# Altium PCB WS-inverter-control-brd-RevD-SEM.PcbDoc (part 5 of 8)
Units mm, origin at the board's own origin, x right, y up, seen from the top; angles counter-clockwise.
Board outline 270 x 105.92 mm, 6 copper layers (Top Layer, Int1 (Sign), Int2 (PWR), Int3 (GND), Int4 (Sign), Bottom Layer), stack 1.509 mm thick; 709 components, 375 nets, 2377 pads, 1332 vias.
Unrouted connection lines stored in the file: 55.
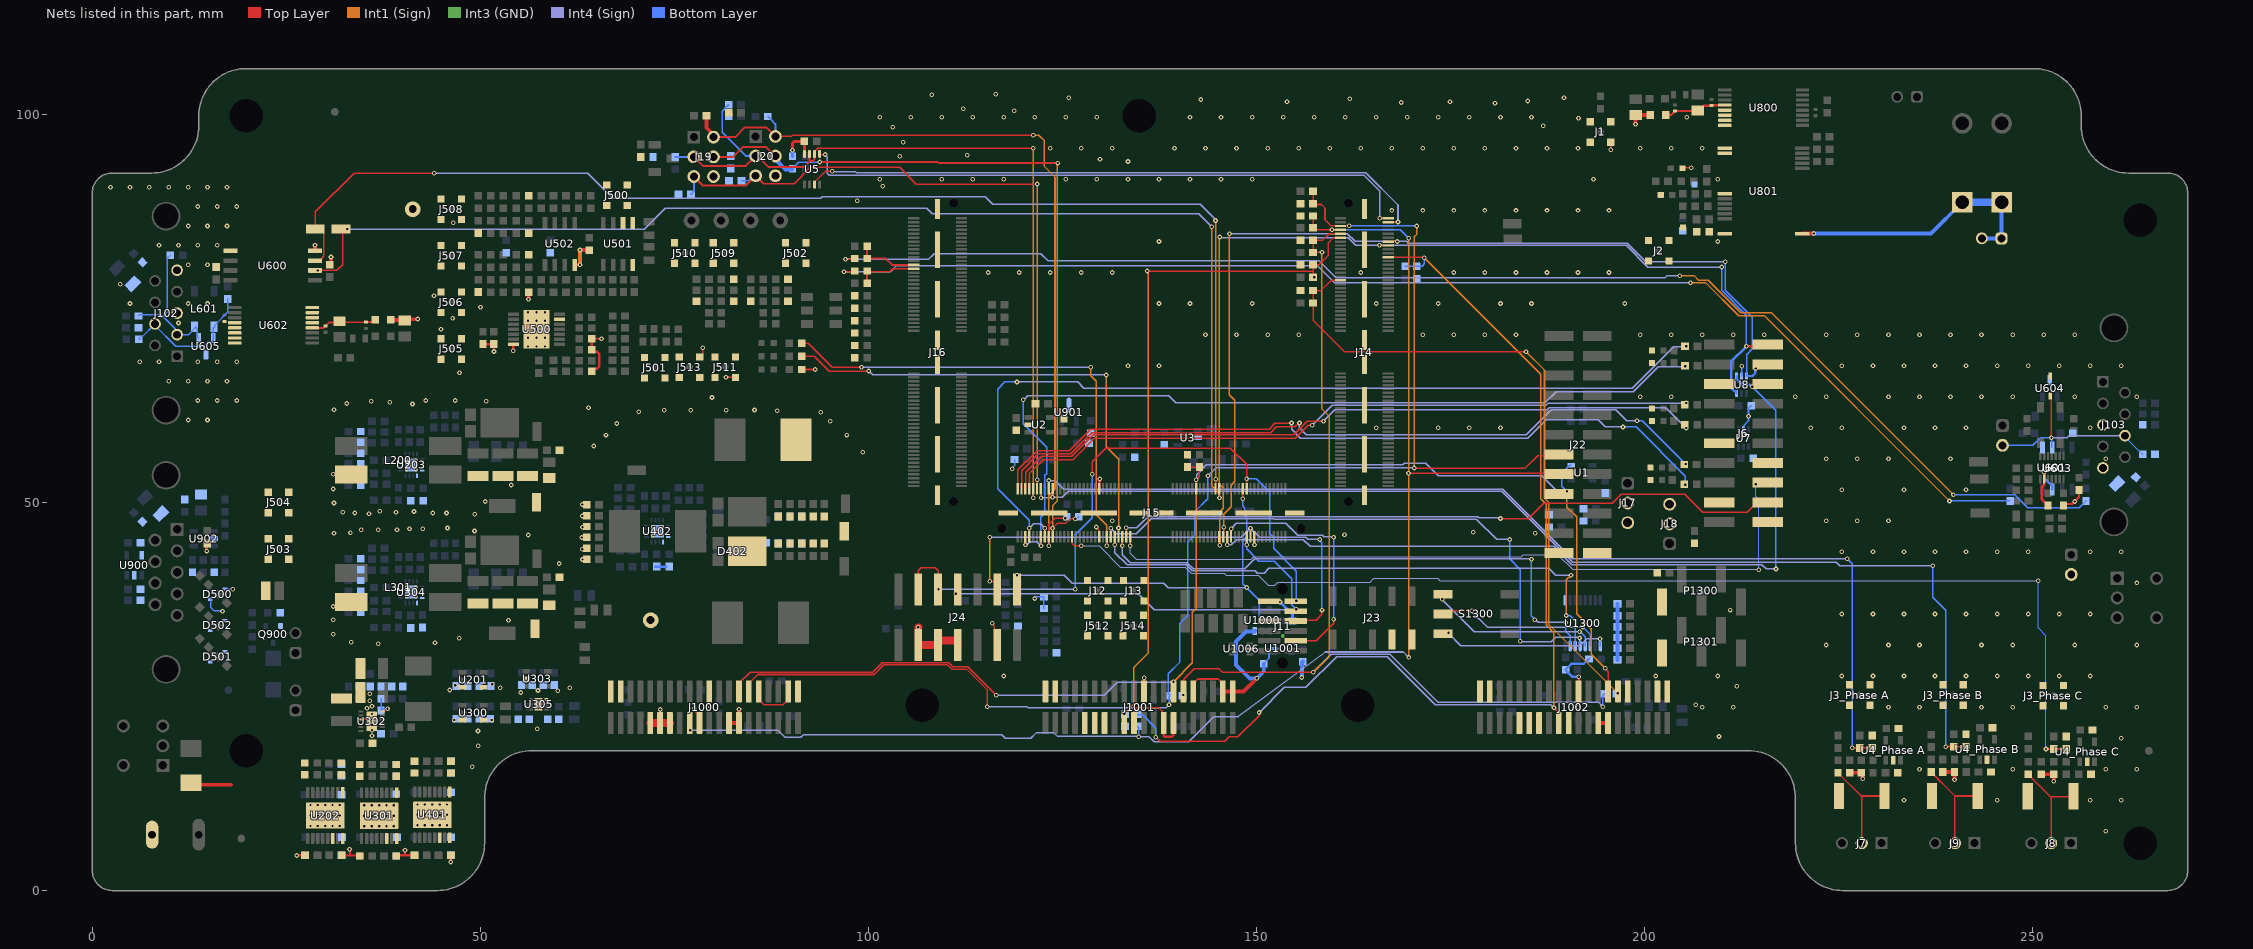
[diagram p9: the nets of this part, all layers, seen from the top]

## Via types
v1: diameter 0.6, hole 0.3, Top Layer to Bottom Layer, tented both sides, 1302 vias
v2: diameter 0.5, hole 0.2, Top Layer to Bottom Layer, 17 vias
v3: diameter 0.6, hole 0.3, Top Layer to Bottom Layer, 12 vias
v4: diameter 0.8, hole 0.5, Top Layer to Bottom Layer, tented both sides, 1 vias

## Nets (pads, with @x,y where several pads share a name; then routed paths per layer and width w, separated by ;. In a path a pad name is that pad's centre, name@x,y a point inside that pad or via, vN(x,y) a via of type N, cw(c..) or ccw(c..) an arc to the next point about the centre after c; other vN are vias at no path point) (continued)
GND: "C8_Phase A.1" "C8_Phase B.1" "C8_Phase C.1" "C10_Phase A.2" "C10_Phase B.2" "C10_Phase C.2" "C11_Phase A.2" "C11_Phase B.2" "C11_Phase C.2" "C12_Phase A.2" "C12_Phase B.2" "C12_Phase C.2" "C13_Phase A.2" "C13_Phase B.2" "C13_Phase C.2" "C14_Phase A.1" "C14_Phase B.1" "C14_Phase C.1" "J3_Phase A.2" "J3_Phase A.3" "J3_Phase A.4" "J3_Phase A.5" "J3_Phase B.2" "J3_Phase B.3" "J3_Phase B.4" "J3_Phase B.5" "J3_Phase C.2" "J3_Phase C.3" "J3_Phase C.4" "J3_Phase C.5" "R23_Phase A.1" "R23_Phase B.1" "R23_Phase C.1" "R24_Phase A.1" "R24_Phase B.1" "R24_Phase C.1" "U4_Phase A.2" "U4_Phase B.2" "U4_Phase C.2" C2.2 C3d1.1 C3d2.1 C3v3ldc2.2 C3v3ldc.2 C4.2 C5.2 C6.1 C6n.1 C7.2 C9.2 C15.2 C16.2 C17.2 C18.2 C19.2 C20.2 C21.2 C22.2 C23.2 C24.2 C100.2 C102.2 C208.2 C209.2 C210.2 C211.2 C212.2 C213.2 C214.2 C215.2 C216.2 C217.2 C218.2 C220.2 C221.2 C222.2 C223.2 C224.2 C225.2 C227.2 C229.1 C230.2 C231.2 C232.2 C233.2 C234.2 C300.2 C301.2 C302.2 C303.2 C304.2 C305.2 C306.2 C307.2 C308.2 C309.2 C310.2 C311.1 C313.2 C314.2 C315.2 C317.2 C318.2 C319.2 C320.2 C321.2 C322.1 C324.2 C325.2 C326.2 C327.2 C328.2 C330.1 C331.2 C332.2 C333.2 C334.2 C335.2 C339.2 C340.2 C341.2 C342.2 C345.2 C346.2 C402.2 C404.2 C406.2 C407.2 C408.2 C409.2 C410.2 C413.2 C414.2 C415.2 C416.2 C417.2 C418.2 C420.1 C421.2 C422.2 C423.1 C424.1 C425.1 C426.1 C427.1 C428.1 C429.2 C431.1 C435.1 C436.1 C437.2 C438.2 C439.2 C440.2 C441.2 C442.2 C503.2 C504.2 C505.2 C506.1 C507.2 C508.1 C511.1 C512.1 C513.2 C516.2 C517.2 C518.2 C519.1 C520.1 C521.2 C522.2 C525.1 C526.1 C528.1 C531.1 C600.2 C602.1 C603.1 C607.2 C609.2 C610.2 C611.1 C612.1 C804.2 C805.2 C810.1 C900.2 C901.1 C902.2 C903.2 C904.2 C905.1 C906.2 C907.2 C908.2 C1000.1 C1001.1 C1002.1 C1300.2 C1301.1 C1302.2 C1303.2 C1304.2 C1305.2 C1306.2 C1307.2 Cu5c.2 D100.2 D402.3 D500.1 D500.4 D501.1 D501.4 D502.1 D502.4 D600.2 FB601.1 FB800.2 J1.2 J1.3 J1.4 J1.5 J2.2 J2.3 J2.4 J2.5 J6.1 J6.4 J6.12 J6.15 J6.18 J11.1 J12.2 J12.3 J12.4 J12.5 J13.2 J13.3 J13.4 J13.5 J14.A1 J14.A2 J14.A3 J14.A4 J14.A5 J14.A6 J14.A7 J14.A8 J15.17 J15.77 J15.78 J15.A1 J15.A2 J15.A3 J15.A4 J15.A5 J15.A6 J15.A7 J15.A8 J16.A1 J16.A2 J16.A3 J16.A4 J16.A5 J16.A6 J16.A7 J16.A8 J17.2 J17.3 J18.2 J18.3 J19.6 J20.6 J22.23 J22.24 J23.2 J23.4 J24.4 J24.8 J24.10 J24.12 J100.2 J103.3 J103.5 J500.2 J500.3 J500.4 J500.5 J501.2 J501.3 J501.4 J501.5 J502.2 J502.3 J502.4 J502.5 J503.2 J503.3 J503.4 J503.5 J504.2 J504.3 J504.4 J504.5 J505.2 J505.3 J505.4 J505.5 J506.2 J506.3 J506.4 J506.5 J507.2 J507.3 J507.4 J507.5 J508.2 J508.3 J508.4 J508.5 J509.2 J509.3 J509.4 J509.5 J510.2 J510.3 J510.4 J510.5 J511.2 J511.3 J511.4 J511.5 J512.2 J512.3 J512.4 J512.5 J513.2 J513.3 J513.4 J513.5 J514.2 J514.3 J514.4 J514.5 J601.2 J1000.2 J1000.4 J1000.9 J1000.11 J1000.13 J1000.19 J1000.22 J1000.25 J1000.27 J1000.32 J1000.38 J1000.40 J1001.2 J1001.4 J1001.9 J1001.11 J1001.13 J1001.19 J1001.22 J1001.25 J1001.27 J1001.32 J1001.38 J1001.40 J1002.2 J1002.4 J1002.9 J1002.11 J1002.13 J1002.19 J1002.22 J1002.25 J1002.27 J1002.32 J1002.38 J1002.40 L200.2 L301.2 L401.1 NT200.1 NT300.1 NT400.1 P1300.5 P1301.5 Q900.2 R5.1 R8.1 R33.1 R34.1 R43.1 R44.1 R45.1 R46.1 R47.1 R48.1 R49.1 R50.1 R51.1 R52.1 R53.1 R54.1 R56.1 R57.1 R58.1 R100.1 R102.1 R238.1 R239.1 R240.1 R241.1 R303.1 R304.1 R305.1 R306.1 R308.1 R320.1 R321.1 R322.1 R406.1 R410.1 R416.1 R417.1 R506.1 R515.2 R533.2 R560.1 R561.1 R903.1 R907.1 R1304.1 TP100.1 TP101.1 TP202.1 TP302.1 TP402.1 TP403.1 U1.2 U2.2 U3.2 U5.4 U7.2 U8.2 U201.3 U201.4 U202.6 U202.8 U202.9 U202.17@30,9.663 U203.1 U203.16 U203.17 U300.3 U300.4 U301.6 U301.8 U301.9 U301.17@36.957,9.643 U302.9 U302.13 U303.2 U304.1 U304.16 U304.17 U305.3 U305.7@57.5,24 U401.6 U401.8 U401.9 U401.17@43.8,9.743 U402.1 U402.16 U402.17 U500.6 U500.14 U500.15 U501.4 U501.5 U501.6 U502.4 U600.4 U601.2 U603.3 U603.5 U604.3 U801.7 U801.8 U801.9 U801.15 U900.2 U900.5 U901.3 U902.2 U1000.3 U1001.2 U1006.2 U1300.9 | length 180.5
  Top Layer w0.18: Cu5c.2@91.743,96.536 Cu5c.2@91.768,96.511
  Top Layer w0.2: U302.9@34.61,22.05 36.03,22.05 v1(36.043,22.036) ; C505.2@51.738,70.411 51.738,69.474 v1(51.747,69.465) ; R506.1@64.344,71.086 65.593,71.086 v1(65.604,71.098) ; J1000.11@73.159,21.588 v1(73.159,23.32) ; J513.4@78.263,68.756 78.633,69.126 78.633,69.926 v1(78.643,69.936) ; v1(79.509,23.836) J1000.22@79.509,25.653 ; v1(81.643,66.136) 81.663,66.116 J511.4@82.863,66.116 ; J1000.32@85.859,25.653 85.859,24.626 86.543,23.943 88.986,23.943 89.669,24.626 J1000.38@89.669,25.653 ; R8.1@91.414,67.136 v1(93.143,67.136) ; v1(115.943,34.436) 116.243,34.136 116.243,31.986 J24.4@116.593,31.636 ; v1(129.343,46.836) 129.681,46.499 129.681,45.637 J15.77@129.733,45.585 ; J15.78@129.733,51.757 129.783,51.807 129.783,52.986 v1(129.833,53.036) ; J1001.19@134.239,21.588 134.239,23.241 134.541,23.543 137.436,23.543 137.839,23.14 137.839,21.798 J1001.25@138.049,21.588 ; J1001.32@141.859,25.653 141.859,26.681 142.431,27.253 145.097,27.253 145.669,26.681 J1001.38@145.669,25.653 ; U1006.2@149.168,31.136 v1(149.729,31.136) ; J15.17@149.733,45.585 149.743,45.575 149.738,45.57 149.738,44.541 v1(149.743,44.536) ; J11.1@151.65,37.258 151.721,37.187 v1(153.039,37.187) ; v1(195.643,95.436) J1.5@195.643,96.436 ; C6.1@204.9,93.078 204.959,93.136 v1(206.043,93.136)
  Top Layer w0.3: v1(14.744,43.739) 14.744,44.652 C905.1@14.808,44.717 ; v1(26.328,4.521) 26.37,4.563 C209.2@27.4,4.563 ; C208.2@32.125,4.563 32.185,4.503 33.194,4.503 ; v1(33.143,5.336) 33.194,5.285 33.194,4.503 ; C301.2@34.468,4.443 34.408,4.503 33.194,4.503 ; C300.2@39.168,4.443 39.268,4.543 40.291,4.543 ; v1(40.291,5.184) 40.291,4.543 ; C404.2@41.5,4.543 40.291,4.543 ; v1(46.2,3.68) C402.2@46.2,4.543 ; C504.2@50.338,70.411 C505.2@51.738,70.411 ; v1(54.22,69.562) 54.22,70.293 U500.14@54.288,70.361 ; C503.2@64.344,66.911 64.669,67.236 65.017,67.236 65.334,67.553 65.334,69.146 65.073,69.407 64.624,69.407 C506.1@64.344,69.686 R506.1@64.344,71.086 ; v1(77.543,23.436) 77.543,23.312 78.239,22.616 J1000.19@78.239,21.588 ; J1001.22@135.509,25.653 135.543,25.688 v1(135.543,27.436) ; J1001.25@138.049,21.588 138.049,19.951 138.2,19.8 139.1,19.8 139.319,20.019 J1001.27@139.319,21.588 ; J1002.22@191.509,25.653 191.526,25.671 191.526,27.509 v1(191.543,27.526) ; v1(251.483,53.896) 251.5,53.88 U601.2@251.5,53 251.5,52.295 251.211,52.007 251.211,50.389 251.65,49.95 251.675,49.95 252,49.625 C602.1@252,49.6 ; C612.1@254,49.6 254.195,49.795 255.102,49.795 256,50.693 C611.1@256,51.6
  Top Layer w0.35: U5.4@91.768,94.911 Cu5c.2@91.768,96.511
  Top Layer w0.4: v1(90.225,95.398) 90.225,96.27 90.491,96.536 Cu5c.2@91.743,96.536
  Top Layer w0.5: D100.2@12.7,13.89 12.954,13.636 17.843,13.636 ; v1(28.689,83.163) 28.689,82.445 U600.4@28.693,82.441 ; C600.2@30.601,80.649 30.743,80.791 v1(30.743,81.636) ; FB601.1@38.343,73.536 38.377,73.502 40.009,73.502 40.043,73.468 40.192,73.617 41.924,73.617 v1(41.943,73.636) ; v1(56.193,76.185) 56.213,76.204 56.213,77.085 C507.2@56.238,77.111 ; U502.4@62.143,80.611 62.168,80.636 v1(62.843,80.636) ; v1(62.843,82.536) 64.013,82.536 C518.2@64.038,82.511 ; J1000.25@82.049,21.588 J1000.27@83.319,21.588 83.324,21.594 83.324,23.355 v1(83.33,23.36) ; J1001.38@145.669,25.653 J1001.40@146.939,25.653 148.36,25.653 v1(150.043,27.336) ; J1002.25@194.049,21.588 J1002.27@195.319,21.588 ; v1(198.843,98.736) 198.843,99.786 198.978,99.92 FB800.2@200.827,99.92 ; 226.45,15.178 227.95,15.178 228.131,14.997 228.112,14.978 v1(228.112,14.396) ; 238.45,15.278 239.95,15.278 v1(239.951,14.289) ; 251.15,14.978 252.75,14.978 252.758,14.97 v1(252.758,14.086)
  Top Layer w1: J1000.9@71.889,21.588 J1000.11@73.143,21.588 ; J1000.11@73.159,21.588 J1000.13@74.429,21.588 ; v1(106.443,33.936) 106.433,33.926 J24.12@106.433,31.636 J24.10@108.973,31.636 108.973,32.231 111.513,32.231 J24.8@111.513,31.636
  Int3 (GND) w0.2: v1(16.774,35.974) v1@16.812,35.936
  Int3 (GND) w0.5: 153.392,32.785 153.392,32.813
  Int1 (Sign) w0.5: v1(62.843,80.636) v1(62.843,82.536)
  Bottom Layer w0.2: D500.1@15.2,37.549 15.234,37.515 15.234,36.508 15.691,36.051 16.698,36.051 v1(16.774,35.974) ; D500.4@17.1,38.849 17.106,38.843 18.096,38.843 v1(18.102,38.836) ; v1(118.524,54.357) 118.524,54.442 118.843,54.761 C508.1@118.843,55.536 ; v1(121.443,37.636) 121.649,37.842 C512.1@122.618,37.842 C519.1@122.618,36.342 ; C1002.1@150.949,29.218 150.949,29.243 151.624,29.918 151.624,30.771 151.79,30.938 151.794,30.938 152.044,31.188 U1001.2@152.269,31.188 ; U8.2@212.523,66.299 212.523,67.516 v1(212.543,67.536) ; U7.2@212.773,59.424 212.847,59.498 212.847,59.97 213.412,60.535 213.412,62.136 C23.2@213.752,62.477
  Bottom Layer w0.3: v1(14.744,43.739) 14.744,44.677 15.02,44.953 15.067,44.953 15.243,45.129 15.243,45.203 15.393,45.353 U902.2@15.643,45.353 ; C429.2@72.543,41.736 C420.1@73.943,41.736 ; R1304.1@189.843,28.436 189.843,28.411 190.728,27.526 v1(191.543,27.526) ; R1304.1@189.843,28.461 190.59,29.209 192.19,29.209 192.818,29.836 C1300.2@192.843,29.836 ; v1(251.483,53.896) 251.541,53.839 251.541,53.135 252.351,52.325 252.415,52.325 252.565,52.175 U603.3@252.565,51.7
  Bottom Layer w0.4: R57.1@90.221,94.602 v1@90.221,95.402 ; v1(153.039,37.187) 154.643,35.583 C1000.1@154.643,34.736
  Bottom Layer w0.5: 148.038,32.711 147.393,32.067 147.393,29.083 149.14,27.336 v1(150.043,27.336) 150.949,28.242 C1002.1@150.949,29.218 ; 148.038,32.712 148.682,33.356 149.744,33.356 149.794,33.406 U1000.3@149.794,33.438 ; v1(155.852,27.456) 155.871,27.475 155.871,29.365 C1001.1@155.994,29.488 ; C1305.2@196.543,29.714 C1306.2@196.543,31.2 C1307.2@196.543,32.6 C1304.2@196.543,34 C1303.2@196.543,35.4 C1302.2@196.543,36.936
  other v1: 259.443,7.636 35.057,8.293 36.007,8.293 36.957,8.293 37.907,8.293 38.857,8.293 28.1,8.313 29.05,8.313 30,8.313 30.95,8.313 31.9,8.313 41.9,8.393 42.85,8.393 43.8,8.393 44.75,8.393 45.7,8.393 28.1,9.663 31.9,9.663 35.057,9.643 38.857,9.643 41.9,9.743 45.7,9.743 35.057,10.993 36.007,10.993 36.957,10.993 37.907,10.993 38.857,10.993 28.1,11.013 29.05,11.013 30,11.013 30.95,11.013 31.9,11.013 41.9,11.093 42.85,11.093 43.8,11.093 44.75,11.093 45.7,11.093 233.443,11.636 245.443,11.636 257.443,11.636 261.443,11.636 235.443,15.636 247.443,15.636 259.443,15.636 263.443,15.636 48.943,15.936 49.743,18.636 261.443,19.636 209.616,19.853 36.043,19.936 49.698,20.552 36.043,20.636 57.343,20.836 36.043,21.336 46.649,21.962 51.449,21.962 36.043,22.736 35.391,23.498 191.443,23.636 207.443,23.636 211.443,23.636 231.443,23.636 235.443,23.636 243.443,23.636 247.443,23.636 259.443,23.636 263.443,23.636 36.043,23.736 206.606,23.936 35.743,24.436 35.743,25.336 55.202,25.521 59.956,25.743 57.43,25.777 46.043,25.836 61.523,26.119 52.543,26.136 211.906,26.336 46.743,26.436 51.528,26.6 117.443,27.636 201.443,27.636 209.443,27.636 225.443,27.636 229.443,27.636 233.443,27.636 237.443,27.636 241.443,27.636 245.443,27.636 249.443,27.636 253.443,27.636 257.443,27.636 223.443,31.636 231.443,31.636 235.443,31.636 243.443,31.636 247.443,31.636 255.443,31.636 263.443,31.636 36.86,31.808 44.16,31.908 33.36,32.008 47.26,32.508 31.06,33.008 53.63,34.829 31.06,34.908 225.443,35.636 229.443,35.636 233.443,35.636 237.443,35.636 241.443,35.636 245.443,35.636 249.443,35.636 253.443,35.636 257.443,35.636 211.043,36.136 31.06,36.608 263.443,39.636 60.143,42.136 63.157,42.647 225.443,43.636 229.443,43.636 233.443,43.636 237.443,43.636 241.443,43.636 245.443,43.636 249.443,43.636 257.443,43.636 261.443,43.636 63.12,43.991 63.074,45.494 56.16,45.808 161.343,45.836 185.943,46.036 31.144,46.053 33.254,46.104 177.936,46.177 49.243,46.336 34.66,46.508 36.86,46.508 39.26,46.508 40.86,46.608 42.56,46.608 45.76,46.708 63.159,46.805 131.443,47.636 223.443,47.636 227.443,47.636 231.443,47.636 63.108,48.252 49.272,48.488 35.643,48.536 33.792,48.651 43.872,48.646 45.643,48.636 39.134,48.725 32.275,48.758 41.443,48.836 37.027,48.876 63.143,49.736 31.143,49.936 50.643,50.136 255.443,50.136 225.443,51.636 233.443,51.636 241.443,51.636 31.043,51.736 53.985,52.248 31.043,53.636 223.443,55.636 227.443,55.636 231.443,55.636 239.443,55.636 259.443,55.636 99.293,56.486 64.593,57.286 66.193,58.686 97.193,58.686 165.443,59.636 173.443,59.636 177.443,59.636 181.443,59.636 221.443,59.636 225.443,59.636 233.443,59.636 237.443,59.636 241.443,59.636 257.443,59.636 67.593,60.186 95.093,60.486 213.412,61.105 93.843,61.636 70.393,61.686 88.243,61.836 73.693,61.886 77.093,61.886 81.693,61.886 31.143,61.936 85.317,61.916 63.937,62.227 41.261,62.692 32.788,62.75 38.343,62.936 35.94,63.046 50.744,63.053 42.943,63.136 46.743,63.136 79.843,63.536 199.443,63.636 203.443,63.636 219.443,63.636 223.443,63.636 231.443,63.636 235.443,63.636 239.443,63.636 243.443,63.636 247.443,63.636 255.443,63.636 263.443,63.636 47.319,66.738 133.443,67.636 137.443,67.636 225.443,67.636 229.443,67.636 233.443,67.636 237.443,67.636 241.443,67.636 245.443,67.636 249.443,67.636 253.443,67.636 257.443,67.636 261.443,67.636 56.138,70.111 57.238,70.111 58.338,70.111 56.138,71.211 58.338,71.211 143.443,71.636 147.443,71.636 151.443,71.636 155.443,71.636 171.443,71.636 175.443,71.636 179.443,71.636 183.443,71.636 199.443,71.636 203.443,71.636 207.443,71.636 211.443,71.636 215.443,71.636 223.443,71.636 227.443,71.636 231.443,71.636 235.443,71.636 239.443,71.636 243.443,71.636 247.443,71.636 251.443,71.636 255.443,71.636 56.138,72.311 58.338,72.311 44.919,72.338 56.138,73.411 58.338,73.411 46.419,73.738 56.138,74.511 57.238,74.511 58.338,74.511 50.019,75.138 137.443,75.636 141.443,75.636 149.443,75.636 165.443,75.636 173.443,75.636 181.443,75.636 185.443,75.636 197.443,75.636 44.019,76.638 115.443,79.636 119.443,79.636 123.443,79.636 127.443,79.636 131.443,79.636 163.443,79.636 175.443,79.636 179.443,79.636 183.443,79.636 187.443,79.636 191.443,79.636 195.443,79.636 137.443,83.636 209.443,83.636 46.511,86.044 167.443,87.636 171.443,87.636 175.443,87.636 179.443,87.636 183.443,87.636 187.443,87.636 191.443,87.636 195.443,87.636 98.55,88.873 101.843,90.736 101.443,91.636 109.443,91.636 113.443,91.636 117.443,91.636 125.443,91.636 129.443,91.636 133.443,91.636 137.443,91.636 141.443,91.636 145.443,91.636 149.443,91.636 193.443,91.636 209.443,91.636 133.443,93.936 129.843,94.236 104.043,94.636 112.743,94.736 123.443,95.636 127.443,95.636 131.443,95.636 139.443,95.636 143.443,95.636 147.443,95.636 151.443,95.636 155.443,95.636 159.443,95.636 163.443,95.636 167.443,95.636 171.443,95.636 175.443,95.636 179.443,95.636 183.443,95.636 187.443,95.636 191.443,95.636 199.443,95.636 203.443,95.636 207.443,95.636 104.502,96.413 103.143,98.336 186.943,98.536 191.51,99.502 101.443,99.636 105.443,99.636 109.443,99.636 113.443,99.636 117.443,99.636 121.443,99.636 125.443,99.636 129.443,99.636 141.443,99.636 145.443,99.636 149.443,99.636 153.443,99.636 157.443,99.636 161.443,99.636 165.443,99.636 169.443,99.636 173.443,99.636 177.443,99.636 181.443,99.636 185.443,99.636 205.443,99.636 118.798,100.478 112.243,100.736 180.743,101.436 168.643,101.536 153.943,101.636 174.943,101.636 184.943,101.736 142.843,101.936 162.043,102.036 189.643,102.136 125.825,102.166 108.143,102.536 116.421,102.613
  other v2: 57.5,23.45 57.5,24.55 40.52,37.87 41.68,37.87 41.1,38.45 40.52,39.03 41.68,39.03 72.22,45.72 73.343,45.836 72.8,46.3 72.22,46.88 73.38,46.88 40.52,54.27 41.68,54.27 41.1,54.85 40.52,55.43 41.68,55.43
  other v3: 29.05,9.663 30,9.663 30.95,9.663 36.007,9.643 36.957,9.643 37.907,9.643 42.85,9.743 43.8,9.743 44.75,9.743 57.238,71.211 57.238,72.311 57.238,73.411
GND_ISO: C101.2 C601.2 C604.1 C608.2 C614.1 J102.3 J102.5 R101.1 U600.5 U602.12 U602.13 U602.14 U602.15 U602.16 U605.3
  other v1: 12.343,60.636 14.843,60.636 13.593,63.136 16.093,63.136 18.593,63.136 9.843,65.636 12.343,65.636 14.843,65.636 17.343,65.636 6.093,68.136 8.593,68.136 13.593,68.136 16.093,68.136 18.593,68.136 11.093,73.136 4.843,75.636 12.343,75.636 14.843,75.636 3.593,78.136 12.343,80.636 14.843,80.636 8.593,83.136 11.093,83.136 13.593,83.136 16.093,83.136 12.343,85.636 14.843,85.636 17.343,85.636 13.593,88.136 16.093,88.136 18.593,88.136 2.343,90.636 4.843,90.636 7.343,90.636 9.843,90.636 12.343,90.636 14.843,90.636 17.343,90.636
GNDP: C605.1 C606.2 C613.1 FB601.2 U602.4 U602.5 U602.6 U602.7 U602.8 | length 8.8
  Top Layer w0.25: U602.4@28.343,72.511 29.768,72.511 29.993,72.736 30.093,72.736 30.168,72.811 30.168,72.861 30.474,73.167 31.658,73.167 C606.2@31.843,73.352 31.968,73.227 C605.1@35.234,73.227 ; C605.1@35.243,73.236 36.368,73.236 36.543,73.411 FB601.2@36.543,73.536
GNDP1: C800.2 C801.2 C802.1 FB800.1 U800.4 U800.5 U800.6 U800.7 U800.8 | length 8.3
  Top Layer w0.3: FB800.1@202.643,99.936 203.443,99.936 203.843,100.336 203.843,100.386 203.893,100.436 C801.2@203.943,100.436 206.759,100.436 C802.1@206.843,100.52 207.008,100.52 207.624,101.136 C800.2@208.643,101.136 208.693,101.186 208.902,101.186 208.918,101.203 U800.4@210.35,101.203
HSEC101_13: S1300.6 U1300.1 | length 21.7
  Int4 (Sign) w0.2: v1(174.743,33.236) 174.743,33.136 176.343,31.536 191.676,31.536 192.594,32.455 v1(194.278,32.455)
  Bottom Layer w0.2: v1(194.278,32.455) 194.325,32.455 U1300.1@194.325,31.5
HSEC103_13: S1300.5 U1300.3 | length 21.9
  Top Layer w0.2: S1300.5@174.043,35.636 174.443,36.036 v1(177.743,36.036)
  Int4 (Sign) w0.2: v1(177.743,36.036) 177.743,35.955 177.882,35.816 177.882,35.797 179.73,33.95 v1(192.05,33.95)
  Bottom Layer w0.2: v1(192.05,33.95) 193.025,32.975 U1300.3@193.025,31.5
HSEC105_13: S1300.4 U1300.4 | length 22.4
  Top Layer w0.2: v1(173.943,37.536) 173.943,38.076 S1300.4@174.043,38.176
  Int4 (Sign) w0.2: v1(173.943,37.536) 173.943,37.453 178.06,33.336 v1(191.643,33.336)
  Bottom Layer w0.2: v1(191.643,33.336) 191.741,33.336 192.375,32.702 U1300.4@192.375,31.5
HV: J5.1 J5.2 J107.1 J108.1 U801.1 | length 34.6
  Top Layer w0.5: U801.1@220.325,84.653 v1(221.8,84.653)
  Bottom Layer w0.5: v1(221.8,84.653) 236.916,84.653 J108.1@240.952,88.689 ; J5.2@243.473,84.036 J5.1@246.013,84.036 246.013,88.67 J107.1@246.032,88.689
  Bottom Layer w1: J108.1@240.952,88.689 J107.1@246.032,88.689
IFB_I2C_SCL: J6.3 J15.61 | length 95.7
  Top Layer w0.18: v1(133.733,44.446) J15.61@133.733,45.585
  Top Layer w0.25: J6.3@214.298,52.339 214.3,52.336 v1(214.343,52.336)
  Int4 (Sign) w0.16: v1(133.733,44.446) 133.733,43.446 134.497,42.682 149.32,42.682 149.644,43.006 184.096,43.006 184.359,43.27 188.861,43.27 190.759,41.373 214.707,41.373 v1(214.743,41.336)
  Bottom Layer w0.16: v1(214.343,52.336) 214.343,50.836 214.743,50.436 v1(214.743,41.336)
IFB_I2C_SDA: J6.2 J15.63 | length 87.2
  Top Layer w0.18: J15.63@133.233,45.585 v1(133.233,46.746) ; v1(181.443,47.936) 185.046,47.936 186.995,49.886 195.859,49.886 197.009,51.036 205.224,51.036 207.506,48.754 207.506,48.736 213.248,48.736 214.528,50.016 J6.2@215.863,50.016
  Int4 (Sign) w0.18: v1(133.233,46.746) 134.585,46.746 135.996,48.157 152.329,48.157 152.34,48.146 178.533,48.146 178.663,48.017 181.363,48.017 v1(181.443,47.936)
IFB_U: "C13_Phase A.1" "R20_Phase A.2" J15.104 | length 135.3
  Top Layer w0.18: J15.104@123.233,51.757 v1(123.233,52.826)
  Top Layer w0.2: 227.75,18.378 229.35,18.378
  Top Layer w0.25: v1(226.785,18.378) 227.75,18.378
  Int4 (Sign) w0.18: v1(123.233,52.826) 124.11,52.826 125.205,51.732 131.466,51.732 131.469,51.729 181.736,51.729 190.728,42.736 v1(226.143,42.736)
  Bottom Layer w0.18: v1(226.143,42.736) 226.785,42.095 v1(226.785,18.378)
IFB_U_1_N: "R1_Phase A.1" J15.118 | length 95.8
  Top Layer w0.18: J15.118@119.733,51.757 119.733,54.078 121.911,56.255 126.056,56.255 128.801,59 151.821,59 152.567,59.746 154.951,59.746 155.441,60.236 v1(155.543,60.236)
  Top Layer w0.381: v1(205.314,54.957) v1@205.373,54.899
  Int4 (Sign) w0.18: v1(155.543,60.236) 155.616,60.163 155.543,60.09 155.543,59.618 156.411,58.75 184.767,58.75 184.78,58.738 187.994,61.952 196.328,61.952 197.743,60.536 v1(199.043,60.536)
  Bottom Layer w0.18: v1(199.043,60.536) 199.735,60.536 v1(205.314,54.957)
IFB_U_1_P: "R3_Phase A.1" J15.120 | length 97.4
  Top Layer w0.18: J15.120@119.233,51.757 119.233,54.192 121.731,56.689 125.876,56.689 128.621,59.434 151.641,59.434 152.387,60.18 154.471,60.18 v1(154.527,60.236)
  Top Layer w0.381: v1(205.278,52.266) v1@205.278,52.365
  Int4 (Sign) w0.18: v1(154.527,60.236) 154.558,60.205 154.558,59.421 155.676,58.304 184.977,58.304 185.095,58.422 187.334,60.661 194.018,60.661 194.943,59.736 v1(197.243,59.736)
  Bottom Layer w0.18: v1(197.243,59.736) 198.921,59.736 205.278,53.379 v1(205.278,52.266)
IFB_V: "C13_Phase C.1" "R20_Phase C.2" J15.91 | length 152.8
  Top Layer w0.2: J15.91@126.233,45.585 126.286,45.532 126.286,44.694 126.543,44.436 v1(127.443,44.436) ; 252.743,18.236 254.343,18.236
  Top Layer w0.25: v1(251.743,18.236) 252.743,18.236
  Int4 (Sign) w0.16: v1(127.443,44.436) 127.453,44.446 129.716,44.446 132.482,41.68 140.83,41.68 141.602,40.908 145.872,40.908 146.145,40.635 150.224,40.635 151.522,39.336 152.343,39.336 152.743,39.736 153.312,39.736 cw(c153.365,38.848) 153.418,39.736 164.643,39.736 165.143,40.236 173.343,40.236 173.643,39.936 v1(250.743,39.936)
  Bottom Layer w0.16: v1(250.743,39.936) 250.743,33.83 251.743,32.83 v1(251.743,18.236)
IFB_V_1_N: "R1_Phase C.1" J15.114 | length 90.6
  Top Layer w0.2: J15.114@120.733,51.757 120.743,51.767 120.743,52.836 120.743,53.736 122.525,55.518 126.372,55.518 129.131,58.277 155.001,58.277 156.677,59.952 v1(157.195,59.952)
  Top Layer w0.381: v1@205.373,62.599 v1(205.373,62.813)
  Int4 (Sign) w0.2: v1(157.195,59.952) 159.782,62.54 187.285,62.54 187.558,62.813 v1(205.373,62.813)
IFB_V_1_P: "R3_Phase C.1" J15.116 | length 92.2
  Top Layer w0.18: J15.116@120.233,51.757 120.253,51.777 120.253,53.874 122.341,55.962 126.188,55.962 128.947,58.72 154.817,58.72 156.565,60.469 v1(158.64,60.469)
  Top Layer w0.381: v1(205.373,59.599) 205.373,59.999
  Int4 (Sign) w0.18: v1(158.64,60.469) 160.107,61.936 187.45,61.936 187.745,62.232 202.74,62.232 v1(205.373,59.599)
IFB_VOC_U: J6.8 J15.31 U8.1 | length 101.9
  Top Layer w0.18: v1(146.233,44.546) J15.31@146.233,45.585
  Top Layer w0.3: v1@213.873,65.174 v1(213.873,64.926) 213.986,65.039 J6.8@214.298,65.039
  Int4 (Sign) w0.18: v1(146.233,44.546) 146.789,44.546 147.467,45.224 148.152,45.224 156.055,45.225 156.943,44.336 188.336,44.336 190.665,42.008 215.094,42.008 215.666,41.436 v1(216.943,41.436)
  Bottom Layer w0.18: v1(213.873,64.926) 216.943,61.855 v1(216.943,41.436)
  Bottom Layer w0.3: U8.1@211.864,66.291 211.923,66.233 211.923,65.857 212.566,65.214 213.547,65.214 213.835,64.926 v1(213.873,64.926)
IFB_VOC_V: J6.10 J14.106 J15.35 U8.6 | length 128.7
  Top Layer w0.18: J15.35@145.233,45.585 145.246,45.572 145.246,44.504 v1(145.26,44.49) ; v1(165.865,83.136) 165.872,83.129 166.994,83.129 J14.106@167.001,83.122
  Top Layer w0.3: v1(213.141,70.119) J6.10@214.298,70.119
  Int1 (Sign) w0.18: v1(145.26,44.49) 145.26,48.753 145.743,49.236 145.743,51.872 145.242,52.373 145.242,84.194 v1(145.264,84.216)
  Int4 (Sign) w0.18: v1(145.264,84.216) 145.343,84.136 161.832,84.136 162.832,83.136 v1(165.865,83.136) 197.643,83.136 200.443,80.336 v1(209.943,80.336)
  Bottom Layer w0.18: v1(209.943,80.336) 209.943,77.336 213.141,74.138 v1(213.141,70.119)
  Bottom Layer w0.3: U8.6@211.873,64.049 211.873,64.274 211.823,64.324 211.598,64.324 211.173,64.749 211.173,68.15 v1(213.141,70.119)
IFB_VOC_W: J6.9 J14.108 J15.33 U8.3 | length 124.9
  Top Layer w0.18: J15.33@145.733,45.585 145.76,45.612 145.76,46.791 v1(145.787,46.818) ; J14.108@167.001,83.622 167.016,83.636 v1(168.143,83.636)
  Int1 (Sign) w0.18: v1(145.787,46.818) 145.787,48.481 146.743,49.436 146.743,50.261 146.739,50.265 146.739,52.232 147.223,52.716 147.223,63.156 146.525,63.855 v1(146.525,84.645)
  Int4 (Sign) w0.18: v1(146.525,84.645) 161.719,84.645 162.728,83.636 v1(168.143,83.636) 169.35,83.636 169.57,83.416 197.759,83.416 197.839,83.336 197.843,83.336 200.143,81.036 210.443,81.036 v1(210.429,81.022)
  Bottom Layer w0.18: v1@210.437,81.013 210.437,77.339 213.893,73.883 213.893,69.786 213.173,69.066 U8.3@213.173,66.299
  Bottom Layer w0.3: U8.3@213.173,66.299 213.921,66.299 214.282,66.659 214.282,67.204 v1(214.339,67.261)
IFB_W: "C13_Phase B.1" "R20_Phase B.2" J15.102 J15.108 | length 148.1
  Top Layer w0.18: J15.108@122.233,51.757 122.243,51.747 122.243,50.631 v1(122.253,50.621) ; v1(123.733,50.663) J15.102@123.733,51.757
  Top Layer w0.2: 239.843,18.536 241.443,18.536
  Top Layer w0.25: v1(238.843,18.536) 239.843,18.536
  Int4 (Sign) w0.18: v1(122.253,50.621) 122.274,50.642 123.712,50.642 v1(123.733,50.663) 124.978,50.663 125.767,51.452 131.35,51.452 131.353,51.449 181.62,51.449 190.781,42.288 224.693,42.288 225.145,41.836 v1(237.143,41.836)
  Bottom Layer w0.18: v1(237.143,41.836) 237.143,37.788 238.843,36.088 v1@238.843,18.617 ; v1@238.763,18.617 v1(238.843,18.536)
IFB_W_1_N: "R1_Phase B.1" J15.105 J15.113 | length 116.1
  Top Layer w0.18: J15.113@120.733,45.585 v1(120.733,46.687) ; J15.105@122.733,45.585 v1(122.733,46.689)
  Top Layer w0.381: v1@205.343,70.136 v1(205.37,70.136)
  Int4 (Sign) w0.18: v1(119.143,65.536) 126.969,65.536 127.769,64.736 198.404,64.736 203.759,70.092 v1@205.499,70.092 ; v1(120.733,46.687) 121.29,47.244 122.178,47.244 v1(122.733,46.689)
  Bottom Layer w0.18: v1(119.143,65.536) 117.564,65.536 116.643,64.616 116.643,51.8 120.733,47.71 v1(120.733,46.687)
IFB_W_1_P: "R3_Phase B.1" J15.107 J15.115 | length 113
  Top Layer w0.18: J15.115@120.233,45.585 120.238,45.58 120.238,44.541 v1(120.243,44.536) ; v1(122.233,44.446) J15.107@122.233,45.585
  Top Layer w0.381: v1(205.268,67.561) v1@205.343,67.636
  Int4 (Sign) w0.18: v1(119.943,63.236) 120.031,63.236 120.553,63.758 138.675,63.758 139.603,62.83 187.164,62.83 188.637,64.302 198.583,64.302 201.805,67.524 v1@205.398,67.524 ; v1(120.243,44.536) 120.304,44.598 120.471,44.598 120.838,44.965 121.714,44.965 v1(122.233,44.446)
  Bottom Layer w0.18: v1(119.943,63.236) 119.972,63.208 119.972,60.132 122.968,57.136 122.968,53.705 122.743,53.48 122.743,48.594 122.233,48.084 v1(122.233,44.446)
ILEM_A_1: "R21_Phase A.1" "R23_Phase A.2" J7.2 | length 14.4
  Top Layer w0.2: 224.95,15.178 224.95,15.153 227.925,12.178 ; J7.2@228.003,6.103 228.003,12.1 227.925,12.178 ; 230.953,11.128 230.953,12.178 227.925,12.178
ILEM_B_1: "R21_Phase C.1" "R23_Phase C.2" J8.2 | length 13.1
  Top Layer w0.2: 249.45,14.978 249.45,14.953 252.343,12.06 ; J8.2@252.403,6.103 252.403,12 252.343,12.06 ; 255.293,12.136 255.217,12.06 252.343,12.06
"ILEM_B_Phase B": "R21_Phase B.1" "R23_Phase B.2" J9.2 | length 13.4
  Top Layer w0.2: 236.95,15.278 236.95,15.253 240.025,12.178 ; J9.2@240.003,6.103 240.003,12.156 240.025,12.178 ; 242.953,12.178 240.025,12.178
ISOCAN_H_1: J102.7 L601.3 R601.2 R603.2 U605.2 | length 18.2
  Bottom Layer w0.2: R603.2@5.968,71.021 6.343,71.396 6.461,71.396 7.977,72.912 J102.7@8.08,73.015 8.08,72.8 10.743,70.136 14.336,70.136 14.887,70.687 15.393,70.687 15.593,70.887 U605.2@15.593,71.186 15.593,72.461 15.793,72.661 15.793,72.886 17.443,74.536 R601.2@17.443,76.236
ISOCAN_L_1: J102.2 L601.4 R607.1 R610.2 U605.1 | length 19.2
  Bottom Layer w0.2: R607.1@5.943,74.036 6.112,74.205 8.859,74.205 9.065,73.999 ; R610.2@10.043,81.836 10.018,81.836 9.643,81.461 9.648,81.461 9.648,74.582 9.065,73.999 ; U605.1@13.693,71.186 13.532,71.348 13.532,72.423 13.356,72.599 13.293,72.661 13.293,72.536 12.387,71.63 J102.2@10.92,71.63 10.671,71.879 10.671,72.393 9.065,73.999
LDC_COS: J15.103 J19.2 J20.2 R31.1 R35.1 Rjldc2.2 | length 108.3
  Top Layer w0.2: J20.2@88.013,97.176 90.083,97.176 90.243,97.336 v1(121.243,97.336) ; v1(123.233,44.446) J15.103@123.233,45.585 123.233,47.163 124.021,47.951 v1(125.354,47.951)
  Top Layer w0.25: J19.2@80.043,97.076 82.828,97.076 84.078,98.326 86.863,98.326 J20.2@88.013,97.176
  Top Layer w0.5: R31.1@79.143,99.836 79.143,98.288 80.043,97.388 J19.2@80.043,97.076
  Int1 (Sign) w0.2: v1(121.243,97.336) 121.954,97.336 122.677,96.613 122.677,93.299 124.043,91.933 124.043,51.68 123.233,50.87 v1(123.233,44.446)
  Bottom Layer w0.25: R35.1@87.043,99.736 87.068,99.736 87.418,99.386 87.418,99.361 88.013,98.766 J20.2@88.013,97.176
LDC_COS_N: J15.101 J19.4 J20.4 R33.2 R57.2 Rjldc1.2 | length 101.4
  Top Layer w0.18: J15.101@123.733,45.585 v1(123.733,46.699)
  Top Layer w0.2: v1(93.726,93.878) 108.949,93.878 109.083,93.744 124.375,93.744 v1(124.383,93.736) ; v1(123.733,46.699) 124.388,47.354 125.466,47.354 126,47.888 v1(126.638,47.888)
  Top Layer w0.25: J19.4@80.043,94.536 82.561,94.536 83.811,95.786 86.863,95.786 J20.4@88.013,94.636
  Int1 (Sign) w0.2: v1(123.733,46.699) 123.733,49.583 124.343,50.193 v1@124.343,93.704 ; v1(124.383,93.736) v1@124.415,93.704
  Bottom Layer w0.2: R57.2@90.221,93.002 90.221,93.027 91.022,93.828 93.676,93.828 v1(93.726,93.878) ; v1(126.638,47.888) 126.846,47.888 Rjldc1.2@127.113,48.155
  Bottom Layer w0.25: J19.4@80.043,94.536 82.143,94.536 R33.2@82.243,94.636
  Bottom Layer w0.5: J20.4@88.013,94.636 88.013,94.325 88.412,93.927 88.412,93.808 89.289,92.931 90.15,92.931 R57.2@90.221,93.002
LDC_RX_EN: J14.120 U5.1 | length 80
  Top Layer w0.2: U5.1@93.718,94.911 93.793,94.836 v1(94.443,94.836) ; v1(165.898,86.622) J14.120@167.001,86.622
  Int4 (Sign) w0.2: v1(94.443,94.836) 94.443,94.763 94.687,94.519 94.687,92.421 94.931,92.177 163.855,92.177 165.898,90.134 v1(165.898,86.622)
LDC_SIN: J15.112 J19.3 J20.3 R32.1 R36.1 U5.2 U5.3 | length 105.9
  Top Layer w0.18: U5.2@93.068,94.911 93.068,95.236 93.468,95.636 v1(121.243,95.636) ; v1(121.233,50.621) J15.112@121.233,51.757
  Top Layer w0.25: J19.3@77.503,94.536 78.653,93.386 84.223,93.386 J20.3@85.473,94.636 85.742,94.636 87.164,93.214 91.665,93.214 92.435,93.984 ; U5.3@92.435,94.911 92.435,93.984 ; U5.2@93.068,94.911 93.068,94.237 92.816,93.984 92.435,93.984
  Int1 (Sign) w0.18: v1(121.233,50.621) 121.238,50.626 121.238,95.632 v1(121.243,95.636)
  Bottom Layer w0.25: R36.1@75.099,94.536 J19.3@77.503,94.536 ; R32.1@81.993,101.236 81.968,101.236 81.168,100.436 81.168,97.711 84.243,94.636 J20.3@85.473,94.636
LDC_SIN_N: J15.110 J19.5 J20.5 R34.2 R56.2 | length 91.2
  Top Layer w0.18: J20.5@85.473,92.096 86.488,91.081 90.447,91.081 92.537,93.171 104.048,93.171 106.183,91.036 v1(121.743,91.036) ; J15.110@121.733,51.757 121.738,51.762 121.738,52.931 v1(121.743,52.936)
  Top Layer w0.25: J19.5@77.503,91.996 78.653,90.846 84.223,90.846 J20.5@85.473,92.096
  Int1 (Sign) w0.18: v1(121.743,52.936) v1(121.743,91.036)
  Bottom Layer w0.18: R34.2@83.643,91.436 84.585,91.436 85.245,92.096 J20.5@85.473,92.096
  Bottom Layer w0.25: R56.2@77.143,89.736 77.153,89.736 77.503,90.086 J19.5@77.503,91.996
LDC_TX_EN: J14.118 U5.7 | length 81.3
  Top Layer w0.2: U5.7@93.068,90.961 93.068,91.288 94.461,92.681 95.339,92.681 v1(95.343,92.677) ; J14.118@167.001,86.122 167.008,86.129 168.236,86.129 v1(168.243,86.136)
  Int4 (Sign) w0.2: v1(95.343,92.677) 95.379,92.641 98.306,92.641 98.47,92.477 164.103,92.477 168.243,88.336 v1(168.243,86.136)
LED-1_16: J15.73 R26.1 | length 63.5
  Top Layer w0.18: R26.1@91.414,70.536 92.243,70.536 95.343,67.436 v1(99.118,67.436) ; v1(130.733,44.446) J15.73@130.733,45.585
  Int1 (Sign) w0.18: v1(128.643,67.436) 128.643,66.336 129.343,65.636 129.343,48.436 130.733,47.046 v1(130.733,44.446)
  Int4 (Sign) w0.18: v1(99.118,67.436) v1(128.643,67.436)
LED-2_16: J15.67 R17.1 | length 61.7
  Top Layer w0.18: R17.1@91.414,68.836 93.043,68.836 94.95,66.929 v1@100.036,66.929 ; J15.67@132.233,45.585 v1(132.233,46.719)
  Int1 (Sign) w0.18: v1(130.643,66.436) 130.643,57.184 132.233,55.594 132.233,53.039 132.233,52.633 v1(132.233,46.719)
  Int4 (Sign) w0.18: v1(100.043,66.936) 100.049,66.936 100.549,66.436 v1(130.643,66.436)
LIN_1: C610.1 D600.1 J103.8 J600.2 U603.6 | length 26.4
  Top Layer w0.2: D600.1@252.3,63.7 252.443,63.557 v1(252.443,58.336)
  Int4 (Sign) w0.2: v1(252.443,58.336) 254.433,58.336 254.712,58.615 J103.8@261.92,58.615
  Bottom Layer w0.2: J600.2@246.143,57.366 250.051,57.366 251.021,58.336 v1(252.443,58.336) 252.504,58.276 252.504,57.161 U603.6@252.565,57.1 ; J103.8@261.92,58.615 261.92,58.455 264.175,56.2 C610.1@264.2,56.2
LINA/Uart_RX_LDC_16: J16.26 R27.1 R28.1 | length 7.6
  Top Layer w0.25: R27.1@99.843,83.036 R28.1@99.843,81.436 102.243,81.436 103.058,80.622 105.428,80.622 J16.26@105.45,80.599
LINA/Uart_TX_LDC_16: J16.28 R29.1 R30.1 | length 7.8
  Top Layer w0.25: R30.1@99.843,78.236 R29.1@99.843,79.836 99.943,79.736 102.772,79.736 103.158,80.122 J16.28@105.838,80.122
LINA_RX: R28.2 R614.1 | length 175.6
  Top Layer w0.2: v1(97.043,81.336) 98.143,81.336 R28.2@98.243,81.436
  Int1 (Sign) w0.2: v1(204.543,79.236) 206.382,79.236 206.982,78.636 208.238,78.636 212.419,74.456 216.359,74.456 v1(239.815,51)
  Int4 (Sign) w0.2: v1(97.043,81.336) 107.743,81.336 108.473,82.066 122.207,82.066 123.137,81.136 158.08,81.136 160.282,78.934 202.64,78.934 202.943,79.236 v1(204.543,79.236)
  Bottom Layer w0.2: v1(239.815,51) 247.746,51 247.925,50.821 247.925,50.818 249.406,49.336 256.036,49.336 R614.1@256.9,50.2
LINA_TX: R29.2 R615.1 | length 164.5
  Top Layer w0.2: v1(96.863,79.736) 98.143,79.736 R29.2@98.243,79.836
  Int1 (Sign) w0.2: v1(205.943,78.336) 207.872,78.336 212.145,74.063 215.455,74.063 v1(239.318,50.2)
  Int4 (Sign) w0.2: v1(96.863,79.736) 102.843,79.736 103.634,80.527 157.84,80.527 160.034,78.334 160.079,78.334 160.113,78.3 205.907,78.3 v1(205.943,78.336)
  Bottom Layer w0.2: v1(239.318,50.2) R615.1@247.062,50.2
LVSS_EN: J15.48 J22.17 J1000.28 J1001.28 J1002.28 R4.1 R5.2 U1.3 | length 175.1
  Top Layer w0.18: J1000.28@83.319,25.653 83.319,26.681 84.765,28.126 100.533,28.126 101.777,29.37 110.33,29.37 110.843,28.856 112.796,28.856 v1(116.475,25.177) ; R5.2@141.118,54.56 R4.1@142.67,54.56 ; J15.48@142.233,51.757 v1(142.233,52.926) 142.624,53.317 142.624,54.513 R4.1@142.67,54.56 ; R4.1@142.672,54.561 R4.1@142.67,54.56 ; v1(194.943,28.636) 194.943,28.581 195.319,28.206 J1002.28@195.319,25.653
  Int1 (Sign) w0.18: v1(139.316,26.883) 141.763,29.33 141.763,35.871 142.223,36.331 v1@142.223,52.916 ; v1(190.02,51.434) 190.02,49.359 191.247,48.133 191.247,35.64 193.147,33.739 193.147,30.432 v1(194.943,28.636)
  Int4 (Sign) w0.18: v1(116.475,25.177) 130.383,25.177 132.053,26.846 139.279,26.846 v1(139.316,26.883) ; v1(142.233,52.926) 142.314,53.007 142.314,53.59 143.559,54.836 168.843,54.836 169.053,55.046 171.833,55.046 173.463,53.416 186.793,53.416 188.776,51.434 v1(190.02,51.434)
  Bottom Layer w0.18: v1(190.02,51.434) 189.343,52.111 189.343,53.761 190.368,54.786 U1.3@190.568,54.786
LVSS_IN_HS_A: J14.115 J22.13 J1000.30 R37.1 R49.2 R1017.1 | length 186.5
  Top Layer w0.2: J1000.30@84.589,25.653 84.56,25.653 84.56,26.652 85.745,27.836 100.743,27.836 101.987,29.08 110.21,29.08 110.753,28.536 112.633,28.536 115.332,25.838 v1(115.332,23.688) ; R37.1@157.295,90.111 R49.2@157.295,88.511 157.405,88.402 158.378,88.402 158.838,87.942 158.838,86.442 159.61,85.669 J14.115@160.829,85.669 ; J14.115@160.829,85.622 160.847,85.64 161.947,85.64 v1(161.965,85.658) ; v1(170.343,54.436) 184.643,54.436 186.243,56.036 188.833,56.036 J22.13@188.993,56.196
  Int1 (Sign) w0.2: v1(170.343,54.436) 170.343,84.236 170.643,84.536 v1(170.643,85.636)
  Int4 (Sign) w0.2: v1(115.332,23.688) 120.453,23.688 120.601,23.54 136.568,23.54 136.572,23.543 136.986,23.543 136.989,23.54 138.347,23.54 v1(138.743,23.936) ; v1(143.763,53.436) 144.801,54.475 170.305,54.475 v1(170.343,54.436)
  Bottom Layer w0.2: v1(138.743,23.936) 138.743,24.972 R1017.1@138.889,25.117 138.643,25.363 138.643,27.936 140.143,29.436 140.143,34.454 141.143,35.454 141.143,44.922 142.081,45.859 142.081,48.832 143.736,50.488 143.736,53.41 v1(143.763,53.436) ; v1(161.965,85.658) 161.987,85.636 v1(170.643,85.636)
LVSS_IN_HS_B: J14.111 J1001.30 R38.1 R50.2 R1017.2 R1018.1 | length 124.8
  Top Layer w0.2: v1(140.574,25.203) 140.644,25.272 140.644,27.234 141.992,28.582 145.174,28.582 145.65,28.105 157.312,28.105 v1(157.318,28.111) ; R38.1@157.295,82.211 R38.1@157.295,82.586 ; v1(158.443,82.236) 157.695,82.236 157.67,82.261 157.67,82.561 157.32,82.561 R38.1@157.295,82.586 ; J14.111@160.829,84.669 160.782,84.622 159.379,84.622 158.568,83.811 R50.2@157.295,83.811 R38.1@157.295,82.586
  Int1 (Sign) w0.2: v1(157.318,28.111) 159.406,30.199 159.406,61.085 158.443,62.047 v1(158.443,82.236)
  Int4 (Sign) w0.2: v1(157.318,28.111) 159.643,30.436 167.21,30.436 173.39,24.256 194.076,24.256 v1(194.639,23.694)
  Bottom Layer w0.2: R1017.2@140.489,25.117 v1(140.574,25.203) ; v1(194.639,23.694) 194.639,25.136 R1018.1@194.865,25.362
LVSS_IN_HS_C: J14.87 J1002.30 R39.1 R51.2 R1018.2 | length 86.4
  Top Layer w0.2: J14.87@160.829,78.574 160.782,78.622 159.629,78.622 158.318,77.311 R51.2@157.295,77.311 R39.1@157.295,75.711 157.295,73.484 161.343,69.436 v1(184.743,69.436) ; v1(196.54,25.437) J1002.30@196.54,25.797
  Int1 (Sign) w0.2: v1(184.743,69.436) 187.12,67.059 187.12,50.559 187.641,50.038 187.641,34.336 v1(196.54,25.437)
  Bottom Layer w0.2: R1018.2@196.465,25.362 v1(196.54,25.437)
LVSS_IN_LS_A: J14.113 J22.15 J1000.17 R40.1 R52.2 R1015.1 | length 188.8
  Top Layer w0.2: R52.2@157.295,86.911 R40.1@157.295,85.411 157.585,85.122 159.729,85.122 v1(159.743,85.136) ; v1@159.758,85.122 159.765,85.129 160.822,85.129 J14.113@160.829,85.122 ; v1(169.602,53.777) 188.872,53.777 J22.15@188.993,53.656
  Int1 (Sign) w0.2: v1(169.643,30.036) 169.623,30.057 169.623,53.757 v1(169.602,53.777) 169.602,83.995 v1(169.643,84.036)
  Int4 (Sign) w0.2: v1(77.043,20.636) 88.348,20.636 89.244,19.741 91.297,19.741 91.642,20.086 117.17,20.086 117.651,19.606 120.913,19.606 121.608,20.301 123.908,20.301 124.354,19.855 134.559,19.855 134.769,19.855 v1(134.826,19.797) 136.206,19.797 136.835,19.169 141.276,19.169 144.511,22.404 147.646,22.404 147.708,22.466 147.73,22.485 158.883,30.736 168.943,30.736 v1(169.643,30.036)
  Bottom Layer w0.2: R1015.1@134.669,21.145 134.826,20.988 v1(134.826,19.797) ; v1(159.743,85.136) 168.543,85.136 v1(169.643,84.036)
LVSS_IN_LS_B: J14.109 J1001.17 R41.1 R53.2 R1015.2 R1016.1 | length 90.6
  Top Layer w0.2: J1001.17@132.912,20.705 J1001.17@132.943,20.736 ; J1001.17@132.969,21.588 v1(132.969,22.798) ; J1001.17@133.005,22.024 J1001.17@133.005,22.653 ; v1(135.943,79.836) 135.965,79.815 157.295,79.815 ; R41.1@157.295,79.045 157.295,79.815 ; v1(157.438,79.042) R41.1@157.438,79.045 ; J14.109@160.631,84.169 160.531,84.069 159.865,84.069 159.281,83.486 159.281,81.845 158.048,80.611 R53.2@157.295,80.611 157.295,79.815
  Int1 (Sign) w0.2: v1(132.969,22.798) 134.203,24.032 134.203,28.726 136.043,30.567 136.043,79.519 136.02,79.543 136.02,79.76 v1(135.943,79.836)
  Bottom Layer w0.2: R1016.1@133.005,22.653 R1016.1@133.069,22.717 R1015.2@133.069,21.145
LVSS_IN_LS_C: J14.100 J1002.17 R42.1 R54.2 R1016.2 | length 138.6
  Top Layer w0.18: v1(137.043,19.736) 137.577,19.202 145.902,19.202 146.5,19.8 147.607,19.8 150.343,22.536 v1(150.343,22.936) ; J14.100@167.001,81.622 167.044,81.579 171.6,81.579 v1(171.643,81.536) ; v1(188.343,23.536) 188.75,23.129 188.75,21.807 J1002.17@188.969,21.588
  Int1 (Sign) w0.18: v1(171.643,81.536) 186.643,66.536 186.643,50.486 187.351,49.779 187.351,34.216 188.343,33.224 v1(188.343,23.536)
  Int4 (Sign) w0.18: v1(150.343,22.936) 153.574,26.167 156.374,26.167 160.353,30.146 166.833,30.146 173.043,23.936 187.943,23.936 v1(188.343,23.536)
  Bottom Layer w0.18: R1016.2@134.669,22.717 134.739,22.646 135.333,22.646 137.043,20.936 v1(137.043,19.736) ; R42.1@169.145,80.436 R54.2@170.642,80.436 171.343,80.436 171.643,80.736 v1(171.643,81.536)
MCAN_RX: J15.38 TP603.1 U600.3 | length 163.3
  Top Layer w0.18: U600.3@28.693,81.171 29.293,81.171 29.843,81.721 29.843,84.726 29.333,85.236 29.273,85.236 TP603.1@28.743,85.236 28.743,87.436 33.743,92.436 44.043,92.436 v1(44.067,92.413) ; J15.38@144.733,51.757 144.733,53.004 v1(144.743,53.014)
  Int1 (Sign) w0.18: v1(144.725,86.336) 144.743,86.319 v1(144.743,53.014)
  Int4 (Sign) w0.18: v1(44.067,92.413) 63.867,92.413 67.057,89.223 93.888,89.223 94.042,89.377 115.055,89.377 115.995,88.436 142.743,88.436 144.561,86.618 144.561,86.614 144.725,86.45 v1(144.725,86.336)
MCAN_TX: J15.36 TP601.1 U600.2 | length 159
  Top Layer w0.18: v1(29.057,79.898) 31.505,79.898 32.243,80.636 32.243,85.036 TP601.1@32.043,85.236 v1(32.843,85.236) ; v1(145.233,50.605) J15.36@145.233,51.757
  Int1 (Sign) w0.18: v1(144.253,85.546) 144.253,52.17 145.233,51.19 v1(145.233,50.605)
  Int4 (Sign) w0.18: v1(32.843,85.236) 71.12,85.236 73.828,87.944 107.5,87.944 108.208,87.237 142.563,87.237 v1(144.253,85.546)
MCU_QEP_A: J15.71 U1300.5 | length 77.4
  Top Layer w0.18: J15.71@131.233,45.585 v1(131.233,46.67)
  Int4 (Sign) w0.18: v1(131.233,46.67) 131.961,45.942 134.52,45.942 136.455,47.877 152.213,47.877 152.224,47.866 178.313,47.866 180.943,45.236 v1(182.643,45.236) ; v1(184.018,32.135) 184.099,32.054 184.316,32.054 184.334,32.036 187.989,32.036 188.569,32.617 191.563,32.617 v1(191.643,32.536)
  Bottom Layer w0.18: v1(182.643,45.236) 182.643,42.729 184.018,41.354 v1(184.018,32.135) ; v1(191.643,32.536) 191.684,32.496 191.684,31.541 U1300.5@191.725,31.5
MCU_QEP_B: J15.69 U1300.6 | length 72.7
  Top Layer w0.18: J15.69@131.733,45.585 131.738,45.58 131.738,44.541 v1(131.743,44.536)
  Int1 (Sign) w0.18: v1(189.943,35.436) 189.943,40.036 v1(190.543,40.636)
  Int4 (Sign) w0.18: v1(131.743,44.536) 131.743,43.542 133.329,41.956 140.936,41.956 141.714,41.178 149.849,41.178 150.122,40.905 150.983,40.905 151.615,41.536 187.643,41.536 188.543,40.636 v1(190.543,40.636)
  Bottom Layer w0.18: v1(189.943,35.436) 190.443,35.436 191.053,34.826 191.053,31.522 U1300.6@191.075,31.5
MCU_QEP_I: J15.65 U1300.7 | length 71.7
  Top Layer w0.18: v1(132.733,44.446) J15.65@132.733,45.585
  Int4 (Sign) w0.18: v1(132.733,44.446) 132.733,43.246 133.743,42.236 141.052,42.236 141.83,41.458 148.477,41.458 149.756,42.736 185.406,42.736 v1(185.445,42.697) ; v1(185.877,34.9) 185.957,34.9 186.32,34.536 v1(189.843,34.536)
  Bottom Layer w0.18: v1(185.445,42.697) 185.445,35.401 185.877,34.969 v1(185.877,34.9) ; v1(189.843,34.536) 189.843,33.436 190.425,32.855 U1300.7@190.425,31.5
MCU_TCK_16: J11.2 J15.22 J24.9 J24.11 | length 86.6
  Top Layer w0.18: J24.11@106.433,38.786 106.433,41.233 106.8,41.6 108.6,41.6 108.973,41.227 J24.9@108.973,38.786 v1(109.023,38.836) ; v1(128.843,53.636) 128.843,55.236 130.618,57.011 146.637,57.011 148.733,54.914 v1(148.733,53.06) J15.22@148.733,51.757 ; J11.2@155.08,37.258 v1(155.143,37.321)
  Int4 (Sign) w0.18: v1(109.023,38.836) v1(126.643,38.836)
  Bottom Layer w0.18: v1(126.643,38.836) 126.643,45.848 128.843,48.048 v1(128.843,53.636) ; v1(148.733,53.06) 149.989,53.06 151.74,51.309 151.74,45.993 152.226,45.506 152.226,44.073 155.143,41.156 v1(155.143,37.321)
MCU_TDI_16: J11.6 J15.19 J24.3 | length 65.7
  Top Layer w0.18: v1(115.643,39.836) 116.183,39.836 116.593,39.426 J24.3@116.593,38.786 ; J15.19@149.233,45.585 v1(149.233,46.701) ; J11.6@155.08,34.718 155.209,34.846 157.719,34.846 158.443,35.57 v1(158.443,36.136)
  Int1 (Sign) w0.18: v1(115.643,39.836) v1(115.643,45.504)
  Int4 (Sign) w0.18: v1(115.643,45.504) 148.036,45.504 v1(149.233,46.701) 150.43,45.505 156.371,45.505 156.639,45.236 v1(158.143,45.236)
  Bottom Layer w0.18: v1(158.143,45.236) 158.143,45.123 158.443,44.823 v1(158.443,36.136)
MCU_TDO_16: J11.4 J15.21 J24.7 | length 58.2
  Top Layer w0.18: J11.4@155.08,35.988 155.08,36.18 v1(155.144,36.244)
  Top Layer w0.2: J15.21@148.733,45.585 148.738,45.58 148.738,44.541 v1(148.743,44.536)
  Int4 (Sign) w0.18: v1(111.243,38.236) 134.783,38.236 136.855,36.164 155.064,36.164 v1(155.144,36.244)
  Bottom Layer w0.18: v1(148.743,44.536) 148.743,44.029 150.325,42.448 152.31,42.448 154.58,40.178 154.58,36.809 v1(155.144,36.244)
MCU_TMS_16: J11.5 J15.24 J24.1 | length 48.8
  Top Layer w0.18: v1(148.233,50.477) J15.24@148.233,51.757
  Int4 (Sign) w0.18: v1(119.143,40.636) 125.243,40.636 126.262,39.618 138.079,39.618 138.66,39.036 v1(148.743,39.036)
  Bottom Layer w0.18: v1(148.233,50.477) 148.233,49.55 148.493,49.29 148.493,48.403 148.723,48.173 148.723,45.554 148.233,45.064 148.233,39.546 150.381,37.399 150.381,35.36 v1(150.987,34.754)
MCU_XRSn_16: J11.10 J15.29 | length 32.2
  Top Layer w0.18: J15.29@146.733,45.585 146.738,45.59 146.738,46.631 v1(146.743,46.636) ; J11.10@155.08,32.178 157.685,32.178 159.943,34.436 v1(159.943,34.936)
  Int4 (Sign) w0.18: v1(146.743,46.636) 147.415,47.308 151.99,47.308 151.992,47.306 153.778,47.306 155.3,45.785 158.537,45.785 158.705,45.617 159.863,45.617 v1(159.943,45.536)
  Bottom Layer w0.18: v1(159.943,34.936) v1(159.943,45.536)
MODE_3: R319.2 R322.2 U302.6 | length 3.3
  Top Layer w0.2: U302.6@37.39,23.05 37.575,23.05 37.961,23.436 v1(38.043,23.436)
  Bottom Layer w0.2: R322.2@37.2,24.7 R319.2@37.2,23.2 37.436,23.436 v1(38.043,23.436)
